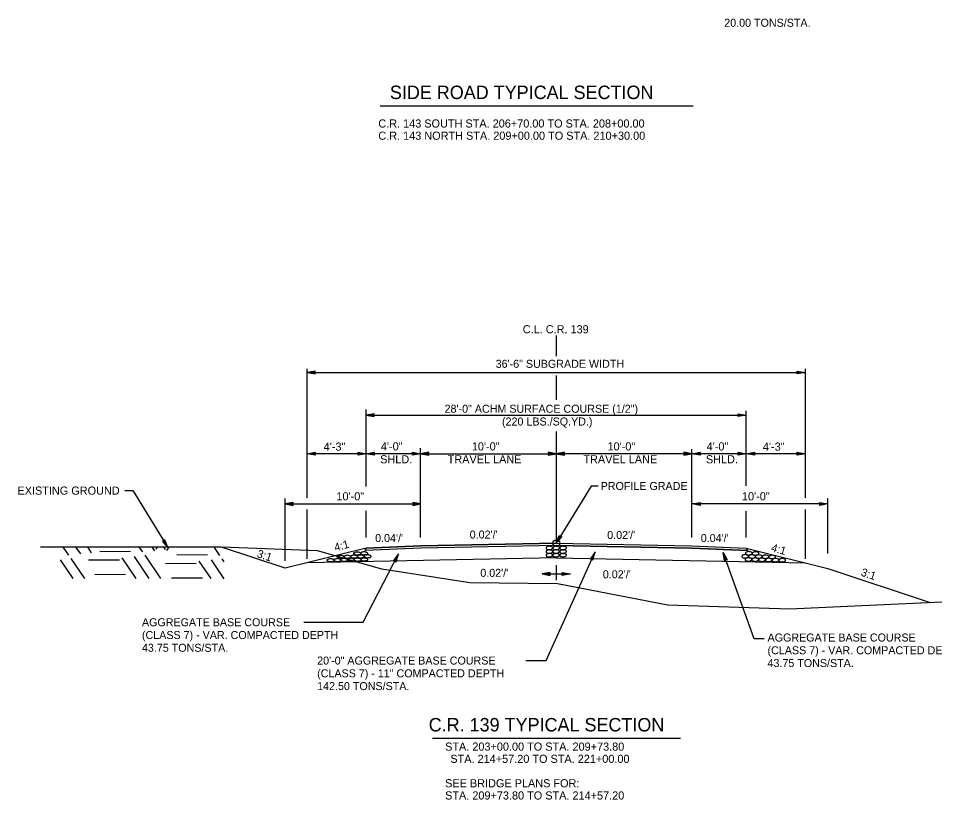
# Model space of a CAD drawing. Extents: x 1734743 to 1735935, y 759845 to 763831.
# Drawn here: x 1735715.7 to 1735783.2, y 762145.7 to 762203.3 of the extents above; entities that cross this region are included whole.
import ezdxf

# ---------------------------------------------------------------- set-up
doc = ezdxf.new("R2010")
doc.units = 0
for name, color, linetype in [('1', 7, 'Continuous'), ('10', 7, 'Continuous'), ('19', 7, 'Continuous'), ('20', 7, 'Continuous'), ('42', 7, 'Continuous'), ('Level 1', 7, 'Continuous'), ('Level 9', 7, 'Continuous'), ('R_Draft', 7, 'Continuous'), ('R_Prop Surface', 7, 'Continuous')]:
    doc.layers.add(name, color=color, linetype=linetype)

# ---------------------------------------------------------------- blocks, each defined once
blk = doc.blocks.new('ROCKS')
at = {"layer": '1'}
blk.add_spline([(0.013, 0.06), (0.053, 0.053), (0.107, 0.033), (0.133, 0.013), (0.133, -0.007), (0.12, -0.033), (0.107, -0.04), (0.073, -0.053), (0.033, -0.067), (0.013, -0.067), (-0.02, -0.06), (-0.06, -0.053), (-0.087, -0.047), (-0.113, -0.02), (-0.113, -0.007), (-0.107, 0.02), (-0.087, 0.033), (-0.067, 0.047), (-0.033, 0.053), (-0.02, 0.06), (0.013, 0.06)], degree=3, dxfattribs=at)

msp = doc.modelspace()

# ---------------------------------------------------------------- linework, layer by layer
at = {"layer": '1'}
msp.add_line((1735742.32, 762196.827), (1735765.379, 762196.827), dxfattribs=at)
for points in [[(1735738.667, 762163.477), (1735738.586, 762163.466), (1735738.478, 762163.429), (1735738.423, 762163.391), (1735738.421, 762163.35), (1735738.447, 762163.296), (1735738.473, 762163.282), (1735738.539, 762163.253), (1735738.619, 762163.223), (1735738.659, 762163.222), (1735738.726, 762163.233), (1735738.807, 762163.244), (1735738.861, 762163.256), (1735738.917, 762163.308), (1735738.917, 762163.334), (1735738.906, 762163.389), (1735738.866, 762163.417), (1735738.827, 762163.445), (1735738.76, 762163.46), (1735738.734, 762163.475), (1735738.667, 762163.477)], [(1735739.163, 762163.487), (1735739.082, 762163.476), (1735738.973, 762163.44), (1735738.918, 762163.401), (1735738.917, 762163.361), (1735738.942, 762163.306), (1735738.969, 762163.292), (1735739.035, 762163.263), (1735739.114, 762163.234), (1735739.155, 762163.233), (1735739.222, 762163.244), (1735739.303, 762163.255), (1735739.357, 762163.266), (1735739.412, 762163.318), (1735739.413, 762163.345), (1735739.401, 762163.399), (1735739.362, 762163.427), (1735739.323, 762163.455), (1735739.256, 762163.471), (1735739.23, 762163.485), (1735739.163, 762163.487)], [(1735739.404, 762163.721), (1735739.323, 762163.71), (1735739.214, 762163.673), (1735739.16, 762163.635), (1735739.158, 762163.594), (1735739.183, 762163.54), (1735739.21, 762163.526), (1735739.276, 762163.497), (1735739.355, 762163.467), (1735739.396, 762163.466), (1735739.463, 762163.477), (1735739.544, 762163.488), (1735739.598, 762163.5), (1735739.653, 762163.552), (1735739.654, 762163.579), (1735739.643, 762163.633), (1735739.603, 762163.661), (1735739.564, 762163.689), (1735739.497, 762163.704), (1735739.471, 762163.719), (1735739.404, 762163.721)], [(1735771.212, 762163.721), (1735771.293, 762163.71), (1735771.401, 762163.673), (1735771.456, 762163.635), (1735771.457, 762163.594), (1735771.432, 762163.54), (1735771.406, 762163.526), (1735771.34, 762163.497), (1735771.26, 762163.467), (1735771.22, 762163.466), (1735771.153, 762163.477), (1735771.072, 762163.488), (1735771.018, 762163.5), (1735770.962, 762163.552), (1735770.961, 762163.579), (1735770.973, 762163.633), (1735771.013, 762163.661), (1735771.052, 762163.689), (1735771.118, 762163.704), (1735771.145, 762163.719), (1735771.212, 762163.721)], [(1735771.453, 762163.487), (1735771.534, 762163.476), (1735771.642, 762163.44), (1735771.697, 762163.401), (1735771.699, 762163.361), (1735771.673, 762163.306), (1735771.647, 762163.292), (1735771.581, 762163.263), (1735771.501, 762163.234), (1735771.461, 762163.233), (1735771.394, 762163.244), (1735771.313, 762163.255), (1735771.259, 762163.266), (1735771.203, 762163.318), (1735771.203, 762163.345), (1735771.214, 762163.399), (1735771.254, 762163.427), (1735771.293, 762163.455), (1735771.36, 762163.471), (1735771.386, 762163.485), (1735771.453, 762163.487)], [(1735771.949, 762163.477), (1735772.03, 762163.466), (1735772.138, 762163.429), (1735772.193, 762163.391), (1735772.194, 762163.35), (1735772.169, 762163.296), (1735772.143, 762163.282), (1735772.077, 762163.253), (1735771.997, 762163.223), (1735771.957, 762163.222), (1735771.889, 762163.233), (1735771.809, 762163.244), (1735771.754, 762163.256), (1735771.699, 762163.308), (1735771.698, 762163.334), (1735771.71, 762163.389), (1735771.749, 762163.417), (1735771.789, 762163.445), (1735771.855, 762163.46), (1735771.882, 762163.475), (1735771.949, 762163.477)]]:
    msp.add_spline(points, degree=3, dxfattribs=at)
at = {"layer": '19'}
for p, q in [((1735755.308, 762178.372), (1735755.308, 762179.908)), ((1735755.308, 762175.171), (1735755.308, 762176.969)), ((1735755.308, 762164.608), (1735755.308, 762172.829)), ((1735736.931, 762171.197), (1735737.531, 762171.302)), ((1735737.531, 762171.092), (1735736.931, 762171.197)), ((1735737.091, 762171.212), (1735737.531, 762171.247)), ((1735737.531, 762171.142), (1735737.091, 762171.182)), ((1735737.531, 762171.302), (1735737.531, 762171.092)), ((1735740.69, 762171.092), (1735740.69, 762171.302)), ((1735740.69, 762171.302), (1735741.29, 762171.197)), ((1735740.69, 762171.247), (1735741.13, 762171.212)), ((1735741.29, 762171.197), (1735740.69, 762171.092)), ((1735741.13, 762171.182), (1735740.69, 762171.142)), ((1735741.29, 762171.197), (1735741.89, 762171.302)), ((1735741.89, 762171.092), (1735741.29, 762171.197)), ((1735741.45, 762171.212), (1735741.89, 762171.247)), ((1735741.89, 762171.142), (1735741.45, 762171.182)), ((1735741.89, 762171.302), (1735741.89, 762171.092)), ((1735744.695, 762171.092), (1735744.695, 762171.302)), ((1735744.695, 762171.302), (1735745.295, 762171.197)), ((1735744.695, 762171.247), (1735745.135, 762171.212)), ((1735745.295, 762171.197), (1735744.695, 762171.092)), ((1735745.135, 762171.182), (1735744.695, 762171.142)), ((1735745.895, 762171.302), (1735745.295, 762171.197)), ((1735745.295, 762171.197), (1735745.895, 762171.092)), ((1735745.895, 762171.247), (1735745.455, 762171.212)), ((1735745.455, 762171.182), (1735745.895, 762171.142)), ((1735745.895, 762171.092), (1735745.895, 762171.302)), ((1735754.695, 762171.302), (1735754.695, 762171.092)), ((1735755.295, 762171.197), (1735754.695, 762171.302)), ((1735755.135, 762171.212), (1735754.695, 762171.247)), ((1735754.695, 762171.092), (1735755.295, 762171.197)), ((1735754.695, 762171.142), (1735755.135, 762171.182)), ((1735755.895, 762171.302), (1735755.295, 762171.197)), ((1735755.295, 762171.197), (1735755.895, 762171.092)), ((1735755.895, 762171.247), (1735755.455, 762171.212)), ((1735755.455, 762171.182), (1735755.895, 762171.142)), ((1735755.895, 762171.092), (1735755.895, 762171.302)), ((1735764.695, 762171.302), (1735764.695, 762171.092)), ((1735765.295, 762171.197), (1735764.695, 762171.302)), ((1735765.135, 762171.212), (1735764.695, 762171.247)), ((1735764.695, 762171.092), (1735765.295, 762171.197)), ((1735764.695, 762171.142), (1735765.135, 762171.182)), ((1735765.295, 762171.197), (1735765.895, 762171.302)), ((1735765.895, 762171.092), (1735765.295, 762171.197)), ((1735765.455, 762171.212), (1735765.895, 762171.247)), ((1735765.895, 762171.142), (1735765.455, 762171.182)), ((1735765.895, 762171.302), (1735765.895, 762171.092)), ((1735768.695, 762171.092), (1735768.695, 762171.302)), ((1735768.695, 762171.302), (1735769.295, 762171.197)), ((1735768.695, 762171.247), (1735769.135, 762171.212)), ((1735769.295, 762171.197), (1735768.695, 762171.092)), ((1735769.135, 762171.182), (1735768.695, 762171.142)), ((1735769.295, 762171.197), (1735769.895, 762171.302)), ((1735769.895, 762171.092), (1735769.295, 762171.197)), ((1735769.455, 762171.212), (1735769.895, 762171.247)), ((1735769.895, 762171.142), (1735769.455, 762171.182)), ((1735769.895, 762171.302), (1735769.895, 762171.092)), ((1735773.059, 762171.092), (1735773.059, 762171.302)), ((1735773.059, 762171.302), (1735773.659, 762171.197)), ((1735773.059, 762171.247), (1735773.499, 762171.212)), ((1735773.659, 762171.197), (1735773.059, 762171.092)), ((1735773.499, 762171.182), (1735773.059, 762171.142)), ((1735735.919, 762167.602), (1735735.319, 762167.497)), ((1735735.319, 762167.497), (1735735.919, 762167.392)), ((1735735.919, 762167.547), (1735735.479, 762167.512)), ((1735735.479, 762167.482), (1735735.919, 762167.442)), ((1735735.919, 762167.392), (1735735.919, 762167.602)), ((1735744.719, 762167.602), (1735744.719, 762167.392)), ((1735745.319, 762167.497), (1735744.719, 762167.602)), ((1735745.159, 762167.512), (1735744.719, 762167.547)), ((1735744.719, 762167.392), (1735745.319, 762167.497)), ((1735744.719, 762167.442), (1735745.159, 762167.482)), ((1735765.308, 762167.497), (1735765.908, 762167.602)), ((1735765.908, 762167.392), (1735765.308, 762167.497)), ((1735765.468, 762167.512), (1735765.908, 762167.547)), ((1735765.908, 762167.442), (1735765.468, 762167.482)), ((1735765.908, 762167.602), (1735765.908, 762167.392)), ((1735774.708, 762167.392), (1735774.708, 762167.602)), ((1735774.708, 762167.602), (1735775.308, 762167.497)), ((1735774.708, 762167.547), (1735775.148, 762167.512)), ((1735775.308, 762167.497), (1735774.708, 762167.392)), ((1735775.148, 762167.482), (1735774.708, 762167.442)), ((1735755.295, 762164.608), (1735755.519, 762165.174)), ((1735755.697, 762165.065), (1735755.295, 762164.608)), ((1735755.369, 762164.749), (1735755.562, 762165.142)), ((1735755.656, 762165.086), (1735755.392, 762164.737)), ((1735755.519, 762165.174), (1735755.697, 762165.065)), ((1735719.367, 762163.718), (1735718.986, 762164.292)), ((1735720.262, 762163.81), (1735719.93, 762164.298)), ((1735721.057, 762163.902), (1735720.795, 762164.297)), ((1735724.821, 762163.957), (1735724.595, 762164.296)), ((1735725.716, 762164.049), (1735725.55, 762164.294)), ((1735725.806, 762164.155), (1735725.913, 762164.305)), ((1735726.511, 762164.141), (1735726.405, 762164.291)), ((1735726.601, 762164.062), (1735726.767, 762164.306)), ((1735730.497, 762163.707), (1735730.105, 762164.29)), ((1735735.319, 762162.754), (1735730.626, 762164.318)), ((1735741.29, 762164.247), (1735735.319, 762162.754)), ((1735741.29, 762164.247), (1735741.205, 762164.077)), ((1735755.295, 762164.608), (1735745.308, 762164.408)), ((1735755.299, 762164.441), (1735745.311, 762164.241)), ((1735755.292, 762164.441), (1735765.279, 762164.241)), ((1735755.295, 762164.608), (1735765.283, 762164.408)), ((1735769.301, 762164.247), (1735775.308, 762162.745)), ((1735769.301, 762164.247), (1735769.386, 762164.077)), ((1735719.694, 762162.002), (1735718.758, 762163.383)), ((1735720.549, 762162), (1735719.553, 762163.475)), ((1735723.103, 762163.358), (1735720.833, 762163.346)), ((1735723.933, 762163.986), (1735721.673, 762163.975)), ((1735724.349, 762161.999), (1735723.317, 762163.531)), ((1735725.304, 762161.996), (1735724.212, 762163.623)), ((1735726.159, 762161.994), (1735725.007, 762163.715)), ((1735729.608, 762163.746), (1735727.348, 762163.725)), ((1735730.814, 762161.99), (1735729.888, 762163.373)), ((1735730.836, 762163.239), (1735730.682, 762163.465)), ((1735755.295, 762163.524), (1735736.931, 762163.157)), ((1735741.065, 762158.788), (1735743.676, 762163.823)), ((1735743.676, 762163.823), (1735743.307, 762163.338)), ((1735743.592, 762163.687), (1735743.356, 762163.316)), ((1735743.45, 762163.267), (1735743.617, 762163.674)), ((1735743.493, 762163.244), (1735743.676, 762163.823)), ((1735754.545, 762155.966), (1735758.154, 762163.967)), ((1735755.295, 762163.524), (1735773.659, 762163.157)), ((1735758.154, 762163.967), (1735757.812, 762163.462)), ((1735757.812, 762163.462), (1735758.003, 762163.378)), ((1735758.077, 762163.827), (1735757.861, 762163.443)), ((1735757.958, 762163.399), (1735758.103, 762163.815)), ((1735758.003, 762163.378), (1735758.154, 762163.967)), ((1735767.694, 762163.313), (1735767.588, 762163.911)), ((1735767.588, 762163.911), (1735767.89, 762163.383)), ((1735769.889, 762157.569), (1735767.588, 762163.911)), ((1735767.74, 762163.331), (1735767.627, 762163.756)), ((1735767.653, 762163.766), (1735767.839, 762163.368)), ((1735767.89, 762163.383), (1735767.694, 762163.313)), ((1735728.768, 762163.117), (1735726.508, 762163.095)), ((1735729.859, 762161.993), (1735728.992, 762163.281)), ((1735743.307, 762163.338), (1735743.493, 762163.244)), ((1735775.308, 762162.745), (1735782.851, 762160.231)), ((1735723.545, 762162.288), (1735721.286, 762162.266)), ((1735729.221, 762162.038), (1735726.95, 762162.025)), ((1735736.704, 762158.788), (1735741.065, 762158.788)), ((1735770.626, 762157.569), (1735769.889, 762157.569)), ((1735753.047, 762155.966), (1735754.545, 762155.966)), ((1735746.188, 762150.237), (1735764.45, 762150.237))]:
    msp.add_line(p, q, dxfattribs=at)
for points in [[(1735758.395, 762168.807), (1735757.878, 762168.807), (1735755.295, 762164.608)], [(1735798.8, 762160.271), (1735783.729, 762160.271), (1735772.478, 762159.75), (1735763.517, 762160.049), (1735755.399, 762161.607), (1735748.929, 762161.681), (1735748.929, 762161.681), (1735742.446, 762162.697), (1735737.711, 762164.033), (1735730.626, 762164.318), (1735717.293, 762164.318)], [(1735769.386, 762164.077), (1735765.278, 762164.242), (1735755.295, 762164.441), (1735745.313, 762164.242), (1735741.205, 762164.077), (1735741.205, 762164.077), (1735741.29, 762164.247), (1735741.29, 762164.247), (1735741.29, 762164.247), (1735745.308, 762164.408), (1735755.295, 762164.608), (1735765.283, 762164.408), (1735769.301, 762164.247), (1735769.301, 762164.247), (1735769.301, 762164.247), (1735769.386, 762164.077), (1735769.386, 762164.077), (1735769.386, 762164.077)]]:
    msp.add_lwpolyline(points, dxfattribs=at)
msp.add_circle((1735755.3, 762164.606), 0.25, dxfattribs=at)
at = {"layer": '20'}
for p, q in [((1735736.931, 762167.946), (1735736.931, 762177.454)), ((1735736.931, 762177.177), (1735773.659, 762177.177)), ((1735773.659, 762167.946), (1735773.659, 762177.454)), ((1735741.29, 762169.298), (1735741.29, 762171.492)), ((1735736.931, 762163.457), (1735736.931, 762167.081)), ((1735773.659, 762163.457), (1735773.659, 762167.081)), ((1735726.452, 762164.847), (1735726.274, 762164.737)), ((1735726.274, 762164.737), (1735726.675, 762164.28)), ((1735726.315, 762164.759), (1735726.579, 762164.41)), ((1735726.602, 762164.421), (1735726.409, 762164.815)), ((1735726.675, 762164.28), (1735726.452, 762164.847))]:
    msp.add_line(p, q, dxfattribs=at)
msp.add_lwpolyline([(1735723.493, 762168.479), (1735724.093, 762168.479), (1735726.675, 762164.28)], dxfattribs=at)
at = {"layer": '42'}
for p, q in [((1735737.531, 762177.282), (1735736.931, 762177.177)), ((1735736.931, 762177.177), (1735737.531, 762177.072)), ((1735737.531, 762177.227), (1735737.091, 762177.192)), ((1735737.091, 762177.162), (1735737.531, 762177.122)), ((1735737.531, 762177.072), (1735737.531, 762177.282)), ((1735773.059, 762177.072), (1735773.059, 762177.282)), ((1735773.059, 762177.282), (1735773.659, 762177.177)), ((1735773.059, 762177.227), (1735773.499, 762177.192)), ((1735773.659, 762177.177), (1735773.059, 762177.072)), ((1735773.499, 762177.162), (1735773.059, 762177.122)), ((1735741.29, 762171.492), (1735741.29, 762174.447)), ((1735769.295, 762171.492), (1735769.295, 762174.367)), ((1735741.89, 762174.143), (1735741.29, 762174.038)), ((1735741.29, 762174.038), (1735769.295, 762174.037)), ((1735741.29, 762174.038), (1735741.89, 762173.933)), ((1735741.89, 762174.088), (1735741.45, 762174.053)), ((1735741.45, 762174.023), (1735741.89, 762173.983)), ((1735741.89, 762173.933), (1735741.89, 762174.143)), ((1735768.695, 762173.932), (1735768.695, 762174.142)), ((1735768.695, 762174.142), (1735769.295, 762174.037)), ((1735768.695, 762174.087), (1735769.135, 762174.052)), ((1735769.295, 762174.037), (1735768.695, 762173.932)), ((1735769.135, 762174.022), (1735768.695, 762173.982)), ((1735755.295, 762162.975), (1735755.295, 762161.888)), ((1735754.848, 762162.445), (1735754.248, 762162.34)), ((1735754.248, 762162.34), (1735754.848, 762162.235)), ((1735754.248, 762162.34), (1735756.343, 762162.34)), ((1735754.848, 762162.39), (1735754.408, 762162.355)), ((1735754.408, 762162.325), (1735754.848, 762162.285)), ((1735754.848, 762162.235), (1735754.848, 762162.445)), ((1735755.743, 762162.235), (1735755.743, 762162.445)), ((1735755.743, 762162.445), (1735756.343, 762162.34)), ((1735755.743, 762162.39), (1735756.183, 762162.355)), ((1735756.343, 762162.34), (1735755.743, 762162.235)), ((1735756.183, 762162.325), (1735755.743, 762162.285))]:
    msp.add_line(p, q, dxfattribs=at)
at = {"layer": 'Level 9'}
for p, q in [((1735741.29, 762168.776), (1735741.29, 762171.492)), ((1735745.295, 762165.033), (1735745.295, 762171.6)), ((1735765.295, 762165.033), (1735765.295, 762171.529)), ((1735769.295, 762168.824), (1735769.295, 762171.492)), ((1735741.29, 762171.197), (1735736.931, 762171.197)), ((1735745.295, 762171.197), (1735741.29, 762171.197)), ((1735745.295, 762171.197), (1735755.295, 762171.197)), ((1735765.295, 762171.197), (1735755.295, 762171.197)), ((1735769.295, 762171.197), (1735765.295, 762171.197)), ((1735773.659, 762171.197), (1735769.295, 762171.197)), ((1735735.319, 762163.305), (1735735.319, 762167.899)), ((1735735.319, 762167.497), (1735745.319, 762167.497)), ((1735775.308, 762167.497), (1735765.308, 762167.497)), ((1735775.308, 762163.844), (1735775.308, 762167.899)), ((1735741.29, 762165.033), (1735741.29, 762166.993)), ((1735769.301, 762165.033), (1735769.301, 762166.976))]:
    msp.add_line(p, q, dxfattribs=at)
at = {"layer": 'R_Prop Surface'}
for p, q in [((1735745.314, 762164.242), (1735741.205, 762164.077)), ((1735745.308, 762164.408), (1735741.29, 762164.247)), ((1735765.276, 762164.242), (1735769.386, 762164.077)), ((1735765.283, 762164.408), (1735769.301, 762164.247))]:
    msp.add_line(p, q, dxfattribs=at)

# ---------------------------------------------------------------- block references
at = {"layer": 'Level 1', "xscale": 2.011654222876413}
for p, yscale, rotation in [((1735754.769, 762164.26), 2.011654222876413, 1.8263814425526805), ((1735754.769, 762163.993), 2.011654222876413, 1.8263814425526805), ((1735755.261, 762163.994), 2.011654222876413, 1.8263814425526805), ((1735755.275, 762164.258), 2.011654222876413, 1.8263814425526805), ((1735755.777, 762164.257), 2.011654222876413, 1.8263814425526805), ((1735755.777, 762163.99), 2.011654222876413, 1.8263814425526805), ((1735739.682, 762163.379), -2.011654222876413, 178.17361855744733), ((1735739.923, 762163.613), -2.011654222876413, 178.17361855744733), ((1735740.178, 762163.39), -2.011654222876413, 178.17361855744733), ((1735740.419, 762163.624), -2.011654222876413, 178.17361855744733), ((1735740.65, 762163.855), -2.011654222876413, 178.17361855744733), ((1735740.673, 762163.399), -2.011654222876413, 178.17361855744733), ((1735740.914, 762163.633), -2.011654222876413, 178.17361855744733), ((1735741.155, 762163.866), -2.011654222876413, 178.17361855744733), ((1735741.17, 762163.412), -2.011654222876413, 178.17361855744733), ((1735741.411, 762163.645), -2.011654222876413, 178.17361855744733), ((1735754.769, 762163.726), 2.011654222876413, 1.8263814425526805), ((1735755.261, 762163.727), 2.011654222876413, 1.8263814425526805), ((1735755.777, 762163.724), 2.011654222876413, 1.8263814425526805), ((1735769.204, 762163.645), 2.011654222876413, 1.8263814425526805), ((1735769.445, 762163.412), 2.011654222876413, 1.8263814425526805), ((1735769.46, 762163.866), 2.011654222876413, 1.8263814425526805), ((1735769.701, 762163.633), 2.011654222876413, 1.8263814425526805), ((1735769.943, 762163.399), 2.011654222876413, 1.8263814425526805), ((1735769.965, 762163.855), 2.011654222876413, 1.8263814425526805), ((1735770.197, 762163.624), 2.011654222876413, 1.8263814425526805), ((1735770.438, 762163.39), 2.011654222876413, 1.8263814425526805), ((1735770.693, 762163.613), 2.011654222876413, 1.8263814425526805), ((1735770.934, 762163.379), 2.011654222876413, 1.8263814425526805)]:
    msp.add_blockref('ROCKS', p, dxfattribs=dict(at, yscale=yscale, rotation=rotation))

# ---------------------------------------------------------------- texts
at = {"layer": '10'}
for s, p in [('C.R. 143 SOUTH STA. 206+70.00 TO STA. 208+00.00', (1735742.184, 762195.227)), ('C.R. 143 NORTH STA. 209+00.00 TO STA. 210+30.00', (1735742.184, 762194.327))]:
    msp.add_text(s, height=0.6, rotation=359.99538, dxfattribs=at).set_placement(p)
msp.add_text('EXISTING GROUND', height=0.6, dxfattribs=at).set_placement((1735715.591, 762168.179))
at = {"layer": '19'}
for s, height, rotation, p in [('20.00 TONS/STA.', 0.59001, 360, (1735767.676, 762202.652)), ('SIDE ROAD TYPICAL SECTION', 0.98999, 359.99538, (1735743.037, 762197.326)), ('10\'-0"', 0.6, 360, (1735749.074, 762171.437)), ('10\'-0"', 0.6, 360, (1735759.074, 762171.437)), ('TRAVEL LANE', 0.6, 360, (1735747.295, 762170.487)), ('TRAVEL LANE', 0.6, 360, (1735757.295, 762170.487)), ('PROFILE GRADE', 0.59001, 360, (1735758.569, 762168.523)), ("0.02'/'", 0.59, 360, (1735748.918, 762164.947)), ("0.02'/'", 0.59, 360, (1735748.918, 762164.947)), ("0.02'/'", 0.59, 360, (1735759.051, 762164.917)), ("0.02'/'", 0.59, 360, (1735759.051, 762164.917)), ('4:1', 0.59, 14.97822, (1735739.022, 762163.996)), ("0.04'/'", 0.59, 360, (1735741.949, 762164.691)), ("0.04'/'", 0.59, 360, (1735765.945, 762164.691)), ('3:1', 0.59, 341.95443, (1735733.19, 762163.59)), ('4:1', 0.59, 344.53267, (1735771.087, 762164.019)), ("0.02'/'", 0.59, 360, (1735749.7, 762162.127)), ('3:1', 0.59, 341.56505, (1735777.698, 762162.226)), ("0.02'/'", 0.59, 360, (1735758.729, 762162.02)), ('AGGREGATE BASE COURSE', 0.59001, 360, (1735724.767, 762158.485)), ('(CLASS 7) - VAR. COMPACTED DEPTH', 0.59001, 360, (1735724.767, 762157.545)), ('AGGREGATE BASE COURSE', 0.59001, 360, (1735770.865, 762157.361)), ('43.75 TONS/STA.', 0.59001, 360, (1735724.767, 762156.605)), ('(CLASS 7) - VAR. COMPACTED DEPTH', 0.59001, 360, (1735770.865, 762156.421)), ('20\'-0" AGGREGATE BASE COURSE', 0.59001, 360, (1735737.677, 762155.663)), ('43.75 TONS/STA.', 0.59001, 360, (1735770.865, 762155.481)), ('(CLASS 7) - 11" COMPACTED DEPTH', 0.59001, 360, (1735737.677, 762154.723)), ('142.50 TONS/STA.', 0.59001, 360, (1735737.677, 762153.783)), ('C.R. 139 TYPICAL SECTION', 0.98999, 359.99538, (1735745.897, 762150.737)), ('STA. 203+00.00 TO STA. 209+73.80', 0.6, 359.99538, (1735747.106, 762149.32)), ('STA. 214+57.20 TO STA. 221+00.00', 0.6, 359.99538, (1735747.493, 762148.42)), ('SEE BRIDGE PLANS FOR:', 0.6, 359.99538, (1735747.105, 762146.62)), ('STA. 209+73.80 TO STA. 214+57.20', 0.6, 359.99538, (1735747.105, 762145.72))]:
    msp.add_text(s, height=height, rotation=rotation, dxfattribs=at).set_placement(p)
for s, p in [('4\'-3"', (1735738.158, 762171.42)), ('4\'-0"', (1735742.372, 762171.437)), ('4\'-0"', (1735766.377, 762171.437)), ('4\'-3"', (1735770.522, 762171.42)), ('SHLD.', (1735742.318, 762170.487)), ('SHLD.', (1735766.323, 762170.487)), ('10\'-0"', (1735739.098, 762167.76)), ('10\'-0"', (1735768.979, 762167.76))]:
    msp.add_text(s, height=0.6, dxfattribs=at).set_placement(p)
at = {"layer": '42'}
msp.add_text('36\'-6" SUBGRADE WIDTH', height=0.59001, rotation=360, dxfattribs=at).set_placement((1735750.83, 762177.526))
for s, p in [('28\'-0" ACHM SURFACE COURSE (1/2")', (1735747.067, 762174.216)), ('(220 LBS./SQ.YD.)', (1735751.3, 762173.276))]:
    msp.add_text(s, height=0.59001, dxfattribs=at).set_placement(p)
at = {"layer": 'R_Draft'}
msp.add_text('C.L. C.R. 139', height=0.60001, rotation=360, dxfattribs=at).set_placement((1735752.826, 762180.068))

doc.saveas('drawing.dxf')
